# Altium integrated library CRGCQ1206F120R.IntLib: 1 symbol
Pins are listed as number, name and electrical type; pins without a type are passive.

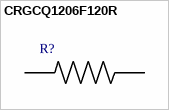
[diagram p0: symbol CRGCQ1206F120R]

## CRGCQ1206F120R
designator R?, comment 1-2176343-4  (value not drawn)
Fixed Resistor CRGCQ 1206 120R 1%; MF: TE Connectivity; MP: CRGCQ1206F120R
footprint *RESC3115X65N
pins: 1, 2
